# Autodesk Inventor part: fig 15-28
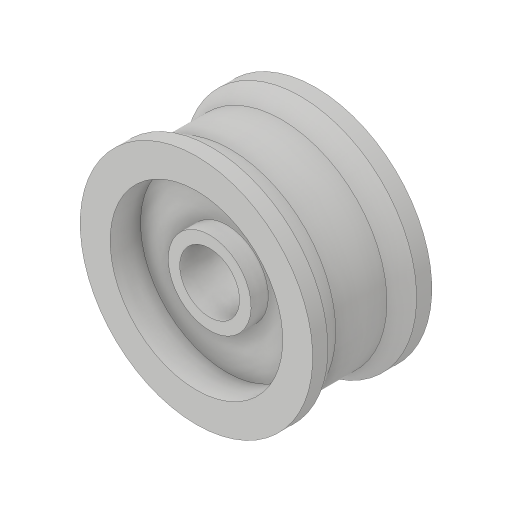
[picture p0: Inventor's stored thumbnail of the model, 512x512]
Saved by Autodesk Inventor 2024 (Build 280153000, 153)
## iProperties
Created: 2018-03
Part Number: fig 15-28
Material: Generic
Document SubType Name: Modeling
Designer: CADCIM 00
Density: 1 g/cm^3
Appearance: Default
Author: CADCIM 00
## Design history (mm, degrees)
sketch "Sketch1"
  geometry: L1 (3.327, 5.31)-(3.327, -4.99); L2 (3.327, -4.99)-(4.606, -4.99); L3 (4.606, -4.99)-(4.606, -3.071); L4 (4.606, -3.071)-(9.597, -3.071); L5 (9.597, -3.071)-(9.597, -6.462); L6 (9.597, -6.462)-(12.924, -6.462); L7 (12.924, -6.462)-(12.924, -4.766); L8 (12.924, -4.766)-(11.708, -2.687); L9 (11.708, -2.687)-(11.708, 0.16); L10 (11.708, 0.16)-(3.327, 0.16); L11 (3.327, 5.31)-(4.606, 5.31); L12 (4.606, 5.31)-(4.606, 3.391); L13 (4.606, 3.391)-(9.597, 3.391); L14 (9.597, 3.391)-(9.597, 6.782); L15 (9.597, 6.782)-(12.924, 6.782); L16 (12.924, 6.782)-(12.924, 5.086); L17 (12.924, 5.086)-(11.708, 3.007); L18 (11.708, 3.007)-(11.708, 0.16); L19 (0, 7.901)-(0, -9.532); 1 further point
  constraints: 38 end point, 7 symmetric about line, 6 perpendicular, 2 vertical, 1 midpoint, 1 parallel
revolve "Revolution1" sketch "Sketch1" stored, may be unused: angle "d0" = 90 deg
body "Solid1"
